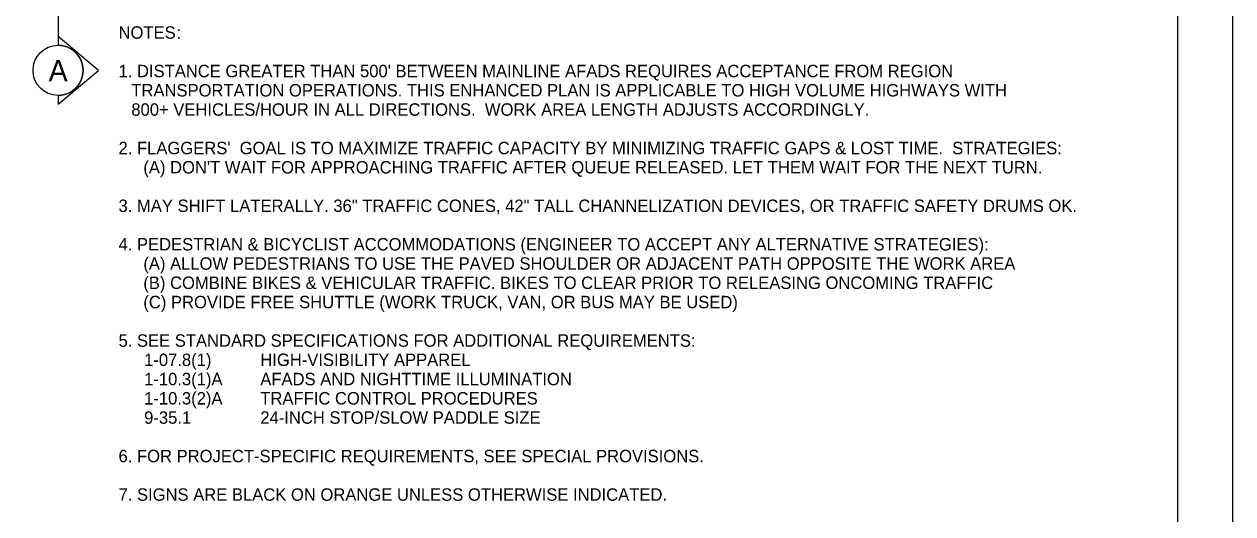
# Model space of a CAD drawing. Extents: x 99999.1 to 100095.7, y 99995 to 100010.7.
# Drawn here: x 100049.24 to 100056.06, y 100002.88 to 100005.64 of the extents above; entities that cross this region are included whole.
import ezdxf

# ---------------------------------------------------------------- set-up
doc = ezdxf.new("R2010")
doc.units = 0
for name, color, linetype in [('SH_GI_GeneralNotesBodyText', 7, 'Continuous'), ('SH_GI_PlotLimits', 7, 'Continuous'), ('SH_GI_SheetBorder', 7, 'Continuous'), ('SH_TI_WZSectionCut', 7, 'Continuous')]:
    doc.layers.add(name, color=color, linetype=linetype)

msp = doc.modelspace()

# ---------------------------------------------------------------- linework, layer by layer
at = {"layer": 'SH_GI_PlotLimits'}
msp.add_lwpolyline([(100039.0625, 99999.6875), (100056.0625, 99999.6875), (100056.0625, 100010.6875), (100039.0625, 100010.6875)], close=True, dxfattribs=at)
at = {"layer": 'SH_GI_SheetBorder'}
msp.add_line((100055.75, 100010.375), (100055.75, 100000), dxfattribs=at)
at = {"layer": 'SH_TI_WZSectionCut'}
for p, q in [((100049.4338, 100007.7022), (100049.4338, 100005.5723)), ((100049.4337, 100005.5723), (100049.4337, 100005.5224)), ((100049.6619, 100005.3812), (100049.4337, 100005.5723)), ((100049.4337, 100005.1901), (100049.6619, 100005.3812)), ((100049.4337, 100005.24), (100049.4337, 100005.1901))]:
    msp.add_line(p, q, dxfattribs=at)
msp.add_circle((100049.4338, 100005.3812), 0.1412, dxfattribs=at)
msp.add_arc((100049.4338, 100005.3812), 0.1412, 269.99779, 90.00221, dxfattribs=at)

# ---------------------------------------------------------------- texts
at = {"layer": 'SH_GI_GeneralNotesBodyText'}
for s, p in [('NOTES', (100049.7751, 100005.5596)), (':', (100050.1026, 100005.5596)), ("1. DISTANCE GREATER THAN 500' BETWEEN MAINLINE AFADS REQUIRES ACCEPTANCE FROM REGION ", (100049.7751, 100005.3426)), ('TRANSPORTATION OPERATIONS. THIS ENHANCED PLAN IS APPLICABLE TO HIGH VOLUME HIGHWAYS WITH     ', (100049.8473, 100005.2341)), ('800+ VEHICLES/HOUR IN ALL DIRECTIONS.  WORK AREA LENGTH ADJUSTS ACCORDINGLY.', (100049.8473, 100005.1256)), ("2. FLAGGERS'  GOAL IS TO MAXIMIZE TRAFFIC CAPACITY BY MINIMIZING TRAFFIC GAPS & LOST TIME.  STRATEGIES:", (100049.7751, 100004.9086)), ("(A) DON'T WAIT FOR APPROACHING TRAFFIC AFTER QUEUE RELEASED. LET THEM WAIT FOR THE NEXT TURN.", (100049.9151, 100004.8001)), ('3. MAY SHIFT LATERALLY. 36" TRAFFIC CONES, 42" TALL CHANNELIZATION DEVICES, OR TRAFFIC SAFETY DRUMS OK.', (100049.7751, 100004.5831)), ('4. PEDESTRIAN & BICYCLIST ACCOMMODATIONS (ENGINEER TO ACCEPT ANY ALTERNATIVE STRATEGIES):', (100049.7751, 100004.3661)), ('(A) ALLOW PEDESTRIANS TO USE THE PAVED SHOULDER OR ADJACENT PATH OPPOSITE THE WORK AREA', (100049.9151, 100004.2576)), ('(B) COMBINE BIKES & VEHICULAR TRAFFIC. BIKES TO CLEAR PRIOR TO RELEASING ONCOMING TRAFFIC', (100049.9151, 100004.1491)), ('(C) PROVIDE FREE SHUTTLE (WORK TRUCK, VAN, OR BUS MAY BE USED)', (100049.9151, 100004.0406)), ('5. SEE STANDARD SPECIFICATIONS FOR ADDITIONAL REQUIREMENTS:', (100049.7751, 100003.8236)), ('1-07.8(1) ', (100049.9195, 100003.7151)), ('HIGH-VISIBILITY APPAREL', (100050.5751, 100003.7151)), ('1-10.3(1)A ', (100049.9195, 100003.6066)), ('AFADS AND NIGHTTIME ILLUMINATION', (100050.5751, 100003.6066)), ('1-10.3(2)A', (100049.9195, 100003.4981)), ('TRAFFIC CONTROL PROCEDURES', (100050.5751, 100003.4981)), ('9-35.1', (100049.9195, 100003.3896)), ('24-INCH STOP/SLOW PADDLE SIZE', (100050.5751, 100003.3896)), ('6. FOR PROJECT-SPECIFIC REQUIREMENTS, SEE SPECIAL PROVISIONS.', (100049.7751, 100003.1726)), ('7. SIGNS ARE BLACK ON ORANGE UNLESS OTHERWISE INDICATED.', (100049.7751, 100002.9556))]:
    msp.add_text(s, height=0.07, rotation=360, dxfattribs=at).set_placement(p)
at = {"layer": 'SH_TI_WZSectionCut'}
msp.add_text('A', height=0.12, rotation=0.00995, dxfattribs=at).set_placement((100049.3808, 100005.3203))

doc.saveas('drawing.dxf')
